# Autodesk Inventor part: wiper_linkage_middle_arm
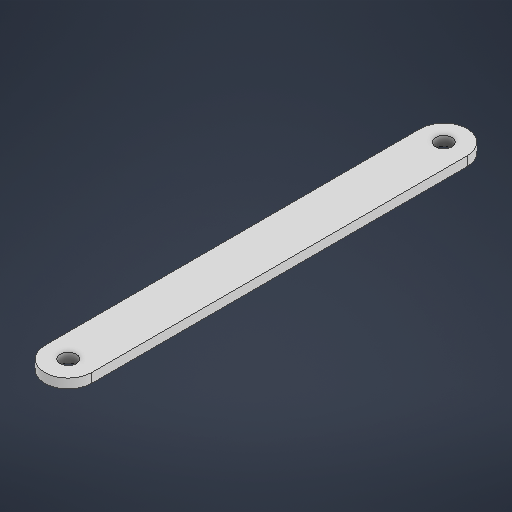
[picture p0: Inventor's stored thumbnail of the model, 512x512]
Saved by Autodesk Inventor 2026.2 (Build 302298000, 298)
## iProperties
Created: 2026-03
Part Number: wiper_linkage_middle_arm
Material: Generic
Document SubType Name: Modeling
Designer: Tathagata Sikdar
Density: 1 g/cm^3
Appearance: Default
Author: Tathagata Sikdar
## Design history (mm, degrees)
sketch "Sketch1"
  geometry: L1 (0, 0)-(0, -90); L2 (-5, -5)-(-5, -85); L3 (5, -85)-(5, -5); C1 r 1.75 at (0, -85); C2 r 1.75 at (0, -5); A1 r 5 centre (0, -5) between (5, -5) and (-5, -5); A2 r 5 centre (0, -85) between (-5, -85) and (5, -85); 1 further point
  constraints: 8 end point, 6 point on circle, 4 centre point, 4 tangent, 2 coincident, 2 point on line, 1 midpoint, 1 parallel, 1 vertical
  dimensions: "d0" = 90 distance of L1.start L1.end; "d1" = 10 diameter of A2; "d2" = 3.5 diameter of C1; "d3" = 3.5 diameter of C2
extrude "Extrusion1" new body sketch "Sketch1" distance "d4" = 2; taper "d5" = 0 deg
body "Solid1"
